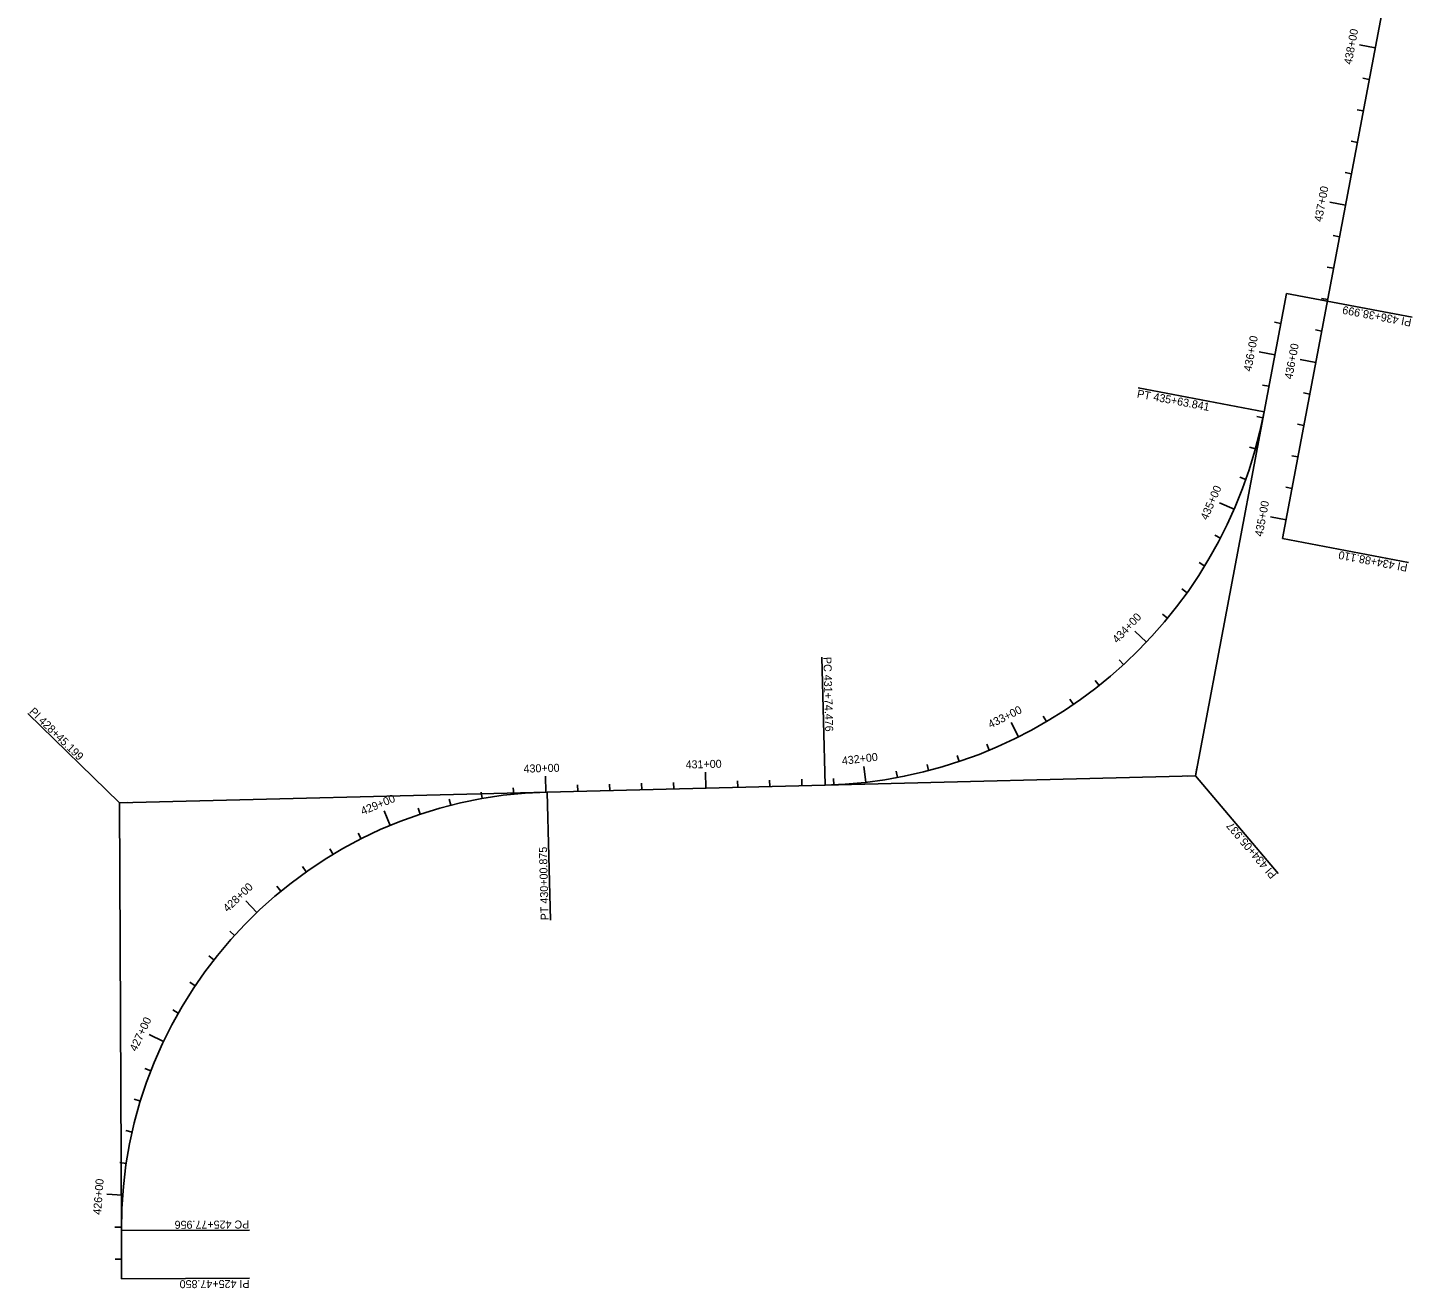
# Model space of a CAD drawing. Extents: x 187748 to 191086, y 249974 to 259749.
# Drawn here: x 187748 to 188613, y 249974 to 250762 of the extents above; entities that cross this region are included whole.
import ezdxf

# ---------------------------------------------------------------- set-up
doc = ezdxf.new("R2010")
doc.units = 0
doc.layers.add('BORDER', color=7, linetype='Continuous')

msp = doc.modelspace()

# ---------------------------------------------------------------- linework, layer by layer
at = {"layer": 'BORDER'}
for p, q in [((188531.98, 250442.67), (188595.21, 250777.42)), ((188589.87, 250749.14), (188580.04, 250751)), ((188586.15, 250729.49), (188582.22, 250730.23)), ((188582.44, 250709.84), (188578.51, 250710.58)), ((188578.73, 250690.19), (188574.8, 250690.93)), ((188575.02, 250670.53), (188571.09, 250671.28)), ((188571.3, 250650.88), (188561.48, 250652.74)), ((188567.59, 250631.23), (188563.66, 250631.97)), ((188563.88, 250611.58), (188559.95, 250612.32)), ((188520.49, 250521.91), (188534.43, 250595.77)), ((188534.43, 250595.77), (188613.04, 250580.92)), ((188560.17, 250591.92), (188556.24, 250592.67)), ((188530.91, 250577.1), (188526.98, 250577.84)), ((188556.46, 250572.27), (188552.53, 250573.01)), ((188527.2, 250557.45), (188517.37, 250559.3)), ((188552.74, 250552.62), (188542.92, 250554.48)), ((188520.49, 250521.91), (188441.88, 250536.76)), ((188523.48, 250537.79), (188519.55, 250538.54)), ((188549.03, 250532.97), (188545.1, 250533.71)), ((188519.75, 250518.15), (188515.83, 250518.94)), ((188545.32, 250513.31), (188541.39, 250514.06)), ((188515.09, 250498.7), (188511.24, 250499.77)), ((188541.61, 250493.66), (188537.68, 250494.4)), ((188509.09, 250479.62), (188505.32, 250480.96)), ((188537.9, 250474.01), (188533.97, 250474.75)), ((188501.77, 250461.02), (188492.6, 250465)), ((188534.18, 250454.36), (188524.36, 250456.21)), ((188493.18, 250442.96), (188489.63, 250444.81)), ((188531.98, 250442.67), (188610.59, 250427.83)), ((188483.34, 250425.55), (188479.93, 250427.64)), ((188472.31, 250408.87), (188469.06, 250411.19)), ((188460.15, 250393), (188457.06, 250395.54)), ((188446.91, 250378.02), (188439.65, 250384.9)), ((188246.14, 250288.7), (188244.14, 250368.67)), ((188432.66, 250363.99), (188429.95, 250366.94)), ((188417.46, 250351), (188414.97, 250354.13)), ((188401.39, 250339.09), (188399.13, 250342.39)), ((187805.43, 250277.69), (187748.04, 250333.43)), ((188366.97, 250318.79), (188362.5, 250327.73)), ((188384.54, 250328.34), (188382.5, 250331.78)), ((188330.05, 250303.47), (188328.78, 250307.26)), ((188348.78, 250310.48), (188347.25, 250314.18)), ((188271.59, 250290.47), (188270.45, 250300.4)), ((188291.36, 250293.44), (188290.63, 250297.37)), ((188310.88, 250297.78), (188309.88, 250301.65)), ((188477.53, 250294.48), (188478.45, 250299.39)), ((188071.71, 250284.34), (188071.43, 250294.34)), ((188072.59, 250284.36), (188246.14, 250288.7)), ((188091.71, 250284.84), (188091.61, 250288.84)), ((188111.7, 250285.34), (188111.6, 250289.34)), ((188131.7, 250285.84), (188131.6, 250289.84)), ((188151.69, 250286.34), (188151.59, 250290.34)), ((188171.68, 250286.84), (188171.43, 250296.83)), ((188191.68, 250287.34), (188191.58, 250291.34)), ((188211.67, 250287.84), (188211.57, 250291.84)), ((188231.66, 250288.34), (188231.57, 250292.33)), ((188251.66, 250288.89), (188251.48, 250292.88)), ((188477.53, 250294.48), (188472.53, 250294.35)), ((188477.53, 250294.48), (188529.34, 250233.52)), ((188031.96, 250280.29), (188031.26, 250284.23)), ((188051.76, 250283.04), (188051.36, 250287.02)), ((188072.59, 250284.36), (188074.59, 250204.39)), ((187805.43, 250277.69), (187810.43, 250277.82)), ((187805.43, 250277.69), (187805.45, 250272.69)), ((187974.49, 250263.47), (187970.64, 250272.7)), ((187993.22, 250270.48), (187991.95, 250274.27)), ((188012.41, 250276.09), (188011.42, 250279.97)), ((187956.32, 250255.11), (187954.52, 250258.68)), ((187938.82, 250245.44), (187936.76, 250248.87)), ((187922.07, 250234.52), (187919.77, 250237.79)), ((187906.17, 250222.4), (187903.63, 250225.49)), ((187891.2, 250209.14), (187884.3, 250216.38)), ((187877.24, 250194.83), (187874.27, 250197.52)), ((187864.36, 250179.53), (187861.21, 250181.99)), ((187852.64, 250163.33), (187849.32, 250165.56)), ((187842.14, 250146.32), (187838.66, 250148.29)), ((187832.91, 250128.58), (187823.87, 250132.87)), ((187825, 250110.21), (187821.27, 250111.66)), ((187818.47, 250091.32), (187814.64, 250092.48)), ((187813.33, 250071.99), (187809.43, 250072.88)), ((187809.62, 250052.34), (187805.67, 250052.94)), ((187807.36, 250032.47), (187797.39, 250033.24)), ((187806.57, 250012.49), (187802.57, 250012.51)), ((187806.57, 250010.45), (187886.57, 250010.79)), ((187806.7, 249980.34), (187806.57, 250010.45)), ((187806.64, 249992.49), (187802.64, 249992.48)), ((187806.7, 249980.34), (187886.69, 249980.69))]:
    msp.add_line(p, q, dxfattribs=at)
for points in [[(188246.14, 250288.7), (188477.53, 250294.48), (188520.49, 250521.91)], [(187806.57, 250010.45), (187805.43, 250277.69), (188072.59, 250284.36)]]:
    msp.add_lwpolyline(points, dxfattribs=at)
for centre, radius, start, end in [((188238.98, 250575.09), 286.48, 271.43056, 349.30366), ((188079.4, 250011.61), 272.84, 91.43057, 180.24362)]:
    msp.add_arc(centre, radius, start, end, dxfattribs=at)

# ---------------------------------------------------------------- texts
for s, rotation, p in [('438+00', 79.30364, (188575.12, 250738.48)), ('437+00', 79.30364, (188556.56, 250640.21)), ('PI 436+38.999', 169.30364, (188612.87, 250579.95)), ('436+00', 79.30364, (188512.45, 250546.76)), ('436+00', 79.30364, (188538, 250541.93)), ('PT 435+63.841', 349.30364, (188440.75, 250530.87)), ('435+00', 66.53541, (188485.03, 250453.84)), ('435+00', 79.30364, (188519.44, 250443.66)), ('PI 434+88.110', 169.30364, (188610.41, 250426.84)), ('434+00', 46.53541, (188428.72, 250376.99)), ('PC 431+74.476', 271.43056, (188245.12, 250368.69)), ('PI 428+45.199', 315.83708, (187748.65, 250334.13)), ('433+00', 26.53541, (188349.52, 250324.04)), ('432+00', 6.53541, (188256.99, 250301.37)), ('430+00', 1.61441, (188057.89, 250296.44)), ('431+00', 1.43056, (188159.12, 250299.01)), ('429+00', 22.61442, (187957.38, 250269.88)), ('PI 434+05.937', 130.3671, (188528.58, 250232.86)), ('PT 430+00.875', 91.43056, (188073.55, 250204.34)), ('428+00', 43.61442, (187872.93, 250209.03)), ('427+00', 64.61442, (187815.88, 250121.94)), ('426+00', 85.61443, (187793.84, 250020.19)), ('PC 425+77.956', 180.2436, (187886.48, 250016.74)), ('PI 425+47.850', 180.2436, (187886.64, 249979.63))]:
    msp.add_text(s, height=5, rotation=rotation, dxfattribs=at).set_placement(p)

doc.saveas('drawing.dxf')
